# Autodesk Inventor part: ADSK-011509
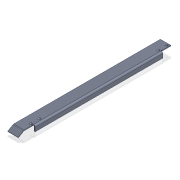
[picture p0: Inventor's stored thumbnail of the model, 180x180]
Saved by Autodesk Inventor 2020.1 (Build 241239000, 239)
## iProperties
Created: 2000-02
Part Number: ADSK-011509
Material: Pearson Stainless Steel
Document SubType Name: Modeling
Designer: sspink
Density: 8.03 g/cm^3
Sheet Metal Rule: Standard
Appearance: Pearson-Stainless
Mass: 940.526 g
Surface Area: 784.045 cm^2
Volume: 117.127 cm^3
Control State: 0
Checked Out: False
Master: False
Shininess: 57.0
Length Units: 11269
Angle Units: 11279
Time Units: 11290
Mass Units: 11283
Length Display Precision: 3
Angle Display Precision: 2
Compacted: True
CUTLENGTH: 2.53 X 24.03 (61 SI)
MATERIAL DESC: SHEET,S/S, 11 GA
MATERIAL_NUMBER: A084638
DocNumber: ADSK-011509.ipt
Folder: 01 - Themengebiete\Simplification\04-Packaging machine\
VDS_Category: 3D Komponenten
Dimensions: 47,6x22,2x607,8 mm
Mass: 0,941 kg
Density: 0.0
Volumn: 0.0
Area: 0.0
PropertySet Name: Model Information
Author: sspink
Revision Number: -
Title: rail
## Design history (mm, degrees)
node "Solide1"
  node "Extrusion1" dims "d2" = 584.2, "d3" = 0
  node "Hole1" dims "d27" = 4.5, "d28" = 10, "d29" = 6.35, "d30" = 90 deg, "d31" = 19.05, "d32" = 118 deg, "d62" = 6
  node "Face1"
  node "Bend3" dims "d44" = 3.175 (= BendRadius), "d58" = 3.175 (= BendReliefWidth), "d59" = 1.5875 (= BendReliefDepth), "d60" = 6.35 (= MinimumRemnant), "d61" = 3.175 (= Thickness), "SeamGap" = 0.00508, "MinimumRemnant" = 6.35 (= 2 x Thickness), "BendReliefWidth" = 3.175 (= Thickness)
  node "Flange1"
node "Plate2" dims "d43" = 3.175 (= BendRadius), "d61" = 3.175 (= Thickness), "MinimumRemnant" = 6.35 (= 2 x Thickness), "BendReliefWidth" = 3.175 (= Thickness)
node "Bend2" dims "d43" = 3.175 (= BendRadius), "d55" = 3.175 (= BendReliefWidth), "d56" = 1.5875 (= BendReliefDepth), "d57" = 6.35 (= MinimumRemnant), "d61" = 3.175 (= Thickness), "SeamGap" = 0.00508, "MinimumRemnant" = 6.35 (= 2 x Thickness), "BendReliefWidth" = 3.175 (= Thickness)
sketch "Sketch5"
  geometry: L1 (41.275, 0)-(0, 0) reference; L2 (0, 0)-(0, -583.349) reference; L3 (33, -8)-(33, -549); 2 further points
  constraints: 2 end point, 2 vertical alignment, 1 vertical
  dimensions: "d23" = 8 distance from line of L3.start L1; "d24" = 34 distance of point (33, -42) L3.start; "d26" = 34 distance of L3.end point (33, -515); "d34" = 33 distance from line of L3.start L2; "d51" = 473 distance of point (33, -515) point (33, -42)
node "Plate1" dims "d38" = 3.175 (= BendRadius), "d61" = 3.175 (= Thickness), "MinimumRemnant" = 6.35 (= 2 x Thickness), "BendReliefWidth" = 3.175 (= Thickness)
node "Bend1" dims "d38" = 3.175 (= BendRadius), "d52" = 3.175 (= BendReliefWidth), "d53" = 1.5875 (= BendReliefDepth), "d54" = 6.35 (= MinimumRemnant), "d61" = 3.175 (= Thickness), "SeamGap" = 0.00508, "MinimumRemnant" = 6.35 (= 2 x Thickness), "BendReliefWidth" = 3.175 (= Thickness)
workplane "Work Plane1"
node "Corps solides"
node "Corps surfaciques"
sketch "Sketch1"
  geometry: L1 (0, 0)-(41.275, 0); L2 (41.275, 0)-(41.275, 3.175); L3 (41.275, 3.175)-(0, 3.175); L4 (0, 3.175)-(0, 0)
  constraints: 8 end point, 2 parallel, 1 horizontal, 1 perpendicular
  dimensions: "d0" = 3.175 distance between parallel lines of L1 L3 (= thickness); "d1" = 41.275 distance between parallel lines of L2 L4
sketch "Sketch6"
  geometry: L1 (41.275, 0)-(0, 0); L2 (0, 0)-(0, 25.4); L3 (0, 25.4)-(41.275, 25.4); L4 (41.275, 25.4)-(41.275, 0)
  constraints: 2 perpendicular
  dimensions: "d36" = 25.4 distance of L1.end L2.end; "d36" = 25.4 distance of L1.start L3.end
sketch "Sketch7"
  geometry: L1 (38.1, -19.05)-(546.1, -19.05); L2 (546.1, -19.05)-(546.1, 3.175); L3 (546.1, 3.175)-(38.1, 3.175); L4 (38.1, 3.175)-(38.1, -19.05); L5 (584.2, 3.175)-(0, 3.175) reference; L6 (0, 3.175)-(0, 0) reference; L7 (584.2, 0)-(584.2, 3.175) reference; L8 (584.2, 0)-(0, 0) reference
  constraints: 8 end point, 2 parallel, 1 collinear, 1 horizontal, 1 perpendicular
  dimensions: "d40" = 38.1 distance between parallel lines of L4 L6; "d41" = 38.1 distance between parallel lines of L2 L7; "d42" = 19.05 distance between parallel lines of L1 L8
other parameters: "thickness" = 3.175 [user parameter; used in 1 equation term], "Thickness" = 3.175, "BendRadius" = 3.175 (= Thickness), "BendReliefDepth" = 1.5875 (= 0.5 x Thickness), "CornerReliefSize" = 7.14375 (= 2.25 x Thickness), "d37" = 30 deg, "d39" = 6.35, "TransitionRadius" = 3.175 (= BendRadius), "TailleRayonJacobi" = 3.175 (= Thickness), "TailleJeu" = 3.175 (= Thickness)
